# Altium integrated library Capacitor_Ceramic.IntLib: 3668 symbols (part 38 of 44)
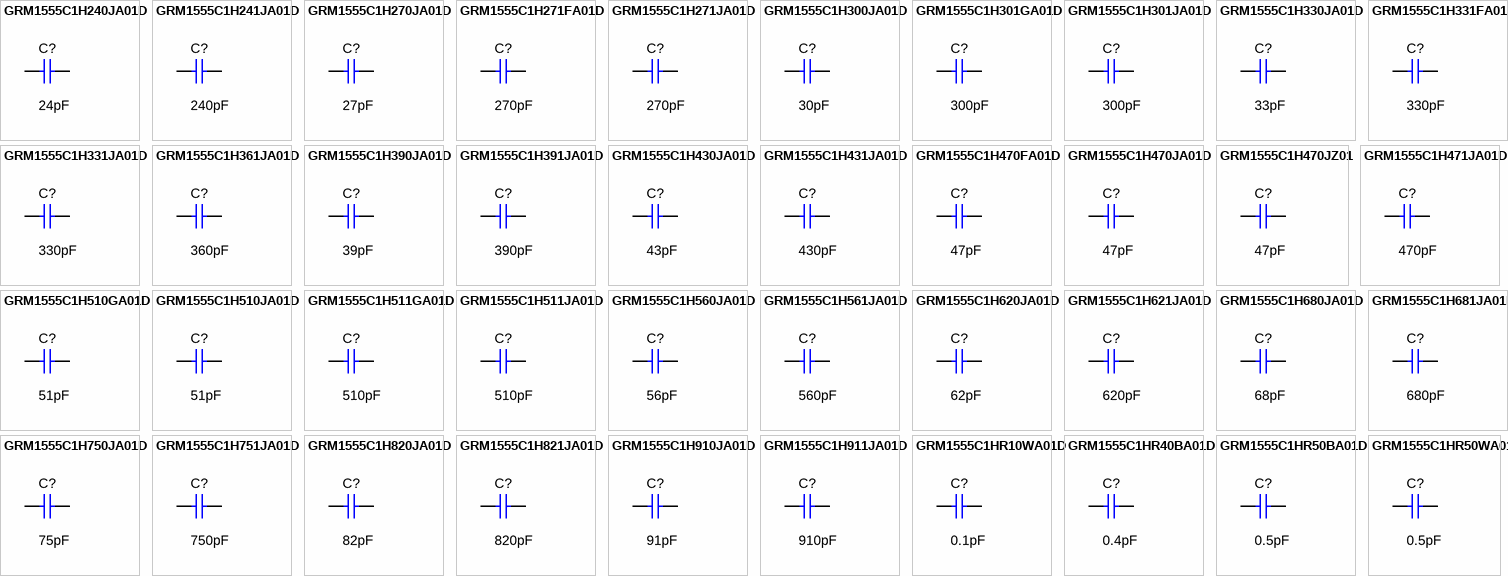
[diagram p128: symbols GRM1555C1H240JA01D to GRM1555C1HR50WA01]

## GRM1555C1H751JA01D
designator C?  ValueDisplayed: 750pF  (hidden comment: GRM1555C1H751JA01D)
CAP, CERM, 750 pF, 50 V,+/- 5%, C0G/NP0, 0402; Manufacturer: MuRata; Polarized: N; CompType: Capacitor; Value: 750pF; U/M: EA; Cap_F: 0.00000000075; Tolerance_%: 5; VDC_V: 50; Value2: 50V; TaMin_C: -55; TaMax_C: 125; Cap_Case: 0402; SizeArea_mm2: 0.5; SizeAreaWB_mm2: 3; SizeX_mm: 1; SizeZ_mm: 0.6; AEC Category: Q200
signal-integrity model Cap
simulation model Cap
footprint 0402
footprint 0402M
footprint 0402L
footprint 0402S
pins: 1, 2

## GRM1555C1H820JA01D
designator C?  ValueDisplayed: 82pF  (hidden comment: GRM1555C1H820JA01D)
CAP, CERM, 82 pF, 50 V,+/- 5%, C0G/NP0, 0402; Manufacturer: MuRata; Polarized: N; CompType: Capacitor; Value: 82pF; U/M: EA; Cap_F: 0.000000000082; Tolerance_%: 5; VDC_V: 50; Value2: 50V; TaMin_C: -55; TaMax_C: 125; Cap_Case: 0402; SizeArea_mm2: 0.5; SizeAreaWB_mm2: 3; SizeX_mm: 1; SizeZ_mm: 0.6; AEC Category: Q200
signal-integrity model Cap
simulation model Cap
footprint 0402
footprint 0402M
footprint 0402L
footprint 0402S
pins: 1, 2

## GRM1555C1H821JA01D
designator C?  ValueDisplayed: 820pF  (hidden comment: GRM1555C1H821JA01D)
CAP, CERM, 820 pF, 50 V,+/- 5%, C0G/NP0, 0402; Manufacturer: MuRata; Polarized: N; CompType: Capacitor; Value: 820pF; U/M: EA; Cap_F: 0.00000000082; Tolerance_%: 5; VDC_V: 50; Value2: 50V; TaMin_C: -55; TaMax_C: 125; Cap_Case: 0402; SizeArea_mm2: 0.5; SizeAreaWB_mm2: 3; SizeX_mm: 1; SizeZ_mm: 0.6; AEC Category: Q200
signal-integrity model Cap
simulation model Cap
footprint 0402
footprint 0402M
footprint 0402L
footprint 0402S
pins: 1, 2

## GRM1555C1H910JA01D
designator C?  ValueDisplayed: 91pF  (hidden comment: GRM1555C1H910JA01D)
CAP, CERM, 91 pF, 50 V,+/- 5%, C0G/NP0, 0402; Manufacturer: MuRata; Polarized: N; CompType: Capacitor; Value: 91pF; U/M: EA; Cap_F: 0.000000000091; Tolerance_%: 5; VDC_V: 50; Value2: 50V; TaMin_C: -55; TaMax_C: 125; Cap_Case: 0402; SizeArea_mm2: 0.5; SizeAreaWB_mm2: 3; SizeX_mm: 1; SizeZ_mm: 0.6; AEC Category: Q200; Green_Lifecycle: Active; Green_REACh: Passed
signal-integrity model Cap
simulation model Cap
footprint 0402
footprint 0402M
footprint 0402L
footprint 0402S
pins: 1, 2

## GRM1555C1H911JA01D
designator C?  ValueDisplayed: 910pF  (hidden comment: GRM1555C1H911JA01D)
CAP, CERM, 910 pF, 50 V,+/- 5%, C0G/NP0, 0402; Manufacturer: MuRata; Polarized: N; CompType: Capacitor; Value: 910pF; U/M: EA; Cap_F: 0.00000000091; Tolerance_%: 5; VDC_V: 50; Value2: 50V; TaMin_C: -55; TaMax_C: 125; Cap_Case: 0402; SizeArea_mm2: 0.5; SizeAreaWB_mm2: 3; SizeX_mm: 1; SizeZ_mm: 0.6; AEC Category: Q200
signal-integrity model Cap
simulation model Cap
footprint 0402
footprint 0402M
footprint 0402L
footprint 0402S
pins: 1, 2

## GRM1555C1HR10WA01D
designator C?  ValueDisplayed: 0.1pF  (hidden comment: GRM1555C1HR10WA01D)
CAP, CERM, 0.1pF, 50 V,+/- 50%, C0G/NP0, 0402; Manufacturer: MuRata; Polarized: N; CompType: Capacitor; U/M: EA; Cap_F: 0.0000000000001; Tolerance_%: 50; Value2: 50V; TaMin_C: -55; TaMax_C: 125; Cap_Case: 0402; SizeArea_mm2: 0.5; SizeAreaWB_mm2: 3; SizeX_mm: 1; SizeZ_mm: 0.6; AEC Category: Q200
signal-integrity model Cap
simulation model Cap
footprint 0402
footprint 0402M
footprint 0402L
footprint 0402S
pins: 1, 2

## GRM1555C1HR40BA01D
designator C?  ValueDisplayed: 0.4pF  (hidden comment: GRM1555C1HR40BA01D)
CAP, CERM, 0.4 pF, 50 V,+/- 25%, C0G/NP0, 0402; Manufacturer: MuRata; Polarized: N; CompType: Capacitor; Value: 0.4pF; U/M: EA; Cap_F: 0.0000000000004; Tolerance_%: 25; VDC_V: 50; Value2: 50V; TaMin_C: -55; TaMax_C: 125; Cap_Case: 0402; SizeArea_mm2: 0.5; SizeAreaWB_mm2: 3; SizeX_mm: 1; SizeZ_mm: 0.6; AEC Category: Q200
signal-integrity model Cap
simulation model Cap
footprint 0402
footprint 0402M
footprint 0402L
footprint 0402S
pins: 1, 2

## GRM1555C1HR50BA01D
designator C?  ValueDisplayed: 0.5pF  (hidden comment: GRM1555C1HR50BA01D)
CAP, CERM, 0.5 pF, 50 V,+/- 20%, C0G/NP0, 0402; Manufacturer: MuRata; Polarized: N; CompType: Capacitor; Value: 0.5pF; U/M: EA; Cap_F: 0.0000000000005; Tolerance_%: 20; VDC_V: 50; Value2: 50V; TaMin_C: -55; TaMax_C: 125; Cap_Case: 0402; SizeArea_mm2: 0.5; SizeAreaWB_mm2: 3; SizeX_mm: 1; SizeZ_mm: 0.6; AEC Category: Q200; Green_Lifecycle: Active; Green_REACh: Passed
signal-integrity model Cap
simulation model Cap
footprint 0402
footprint 0402M
footprint 0402L
footprint 0402S
pins: 1, 2

## GRM1555C1HR50WA01
designator C?  ValueDisplayed: 0.5pF  (hidden comment: GRM1555C1HR50WA01)
CAP, CERM, 0.5 pF, 50 V,+/- 10%, C0G/NP0, 0402; Manufacturer: MuRata; Polarized: N; CompType: Capacitor; Value: 0.5pF; U/M: EA; Cap_F: 0.0000000000005; Tolerance_%: 10; VDC_V: 50; Value2: 50V; TaMin_C: -55; TaMax_C: 125; Cap_Case: 0402; SizeArea_mm2: 0.5; SizeAreaWB_mm2: 3; SizeX_mm: 1; SizeZ_mm: 0.6; AEC Category: Q200
signal-integrity model Cap
simulation model Cap
footprint 0402
footprint 0402M
footprint 0402L
footprint 0402S
pins: 1, 2

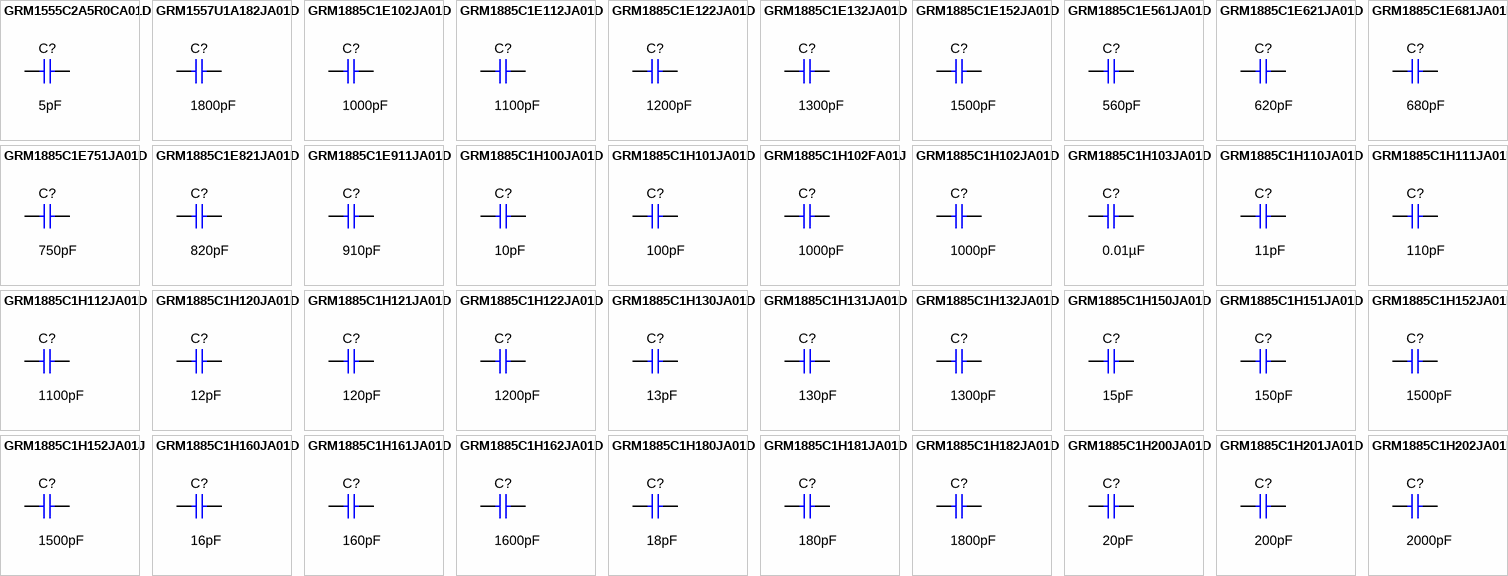
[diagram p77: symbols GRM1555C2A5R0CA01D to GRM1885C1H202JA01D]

## GRM1555C2A5R0CA01D
designator C?  ValueDisplayed: 5pF  (hidden comment: GRM1555C2A5R0CA01D)
CAP, CERM, 5 pF, 100 V,+/- 5%, C0G/NP0, 0402; Manufacturer: MuRata; Polarized: N; CompType: Capacitor; Value: 5pF; U/M: EA; Cap_F: 0.000000000005; Tolerance_%: 5; VDC_V: 100; Value2: 100V; TaMin_C: -55; TaMax_C: 125; Cap_Case: 0402; SizeArea_mm2: 0.5; SizeAreaWB_mm2: 3; SizeX_mm: 1; SizeZ_mm: 0.6; AEC Category: Q200
signal-integrity model Cap
simulation model Cap
footprint 0402
footprint 0402M
footprint 0402L
footprint 0402S
pins: 1, 2

## GRM1557U1A182JA01D
designator C?  ValueDisplayed: 1800pF  (hidden comment: GRM1557U1A182JA01D)
CAP, CERM, 1800 pF, 10 V,+/- 5%, U2J, 0402; Manufacturer: MuRata; Polarized: N; CompType: Capacitor; Value: 1800pF; U/M: EA; Cap_F: 0.0000000018; Tolerance_%: 5; VDC_V: 10; Value2: 10V; TaMin_C: -55; TaMax_C: 125; Cap_Case: 0402; SizeArea_mm2: 0.5; SizeAreaWB_mm2: 3; SizeX_mm: 1; SizeZ_mm: 0.6; AEC Category: Q200
signal-integrity model Cap
simulation model Cap
footprint 0402
footprint 0402M
footprint 0402L
footprint 0402S
pins: 1, 2

## GRM1885C1E102JA01D
designator C?  ValueDisplayed: 1000pF  (hidden comment: GRM1885C1E102JA01D)
CAP, CERM, 1000 pF, 25 V,+/- 5%, C0G/NP0, 0603; Manufacturer: MuRata; Polarized: N; CompType: Capacitor; Value: 1000pF; U/M: EA; Cap_F: 0.000000001; Tolerance_%: 5; VDC_V: 25; Value2: 25V; TaMin_C: -55; TaMax_C: 125; Cap_Case: 0603; SizeArea_mm2: 1.28; SizeAreaWB_mm2: 4.68; SizeX_mm: 1.6; SizeY_mm: 0.8; SizeZ_mm: 1; AEC Category: Q200; Green_Lifecycle: Active; Green_REACh: Passed
signal-integrity model Cap
simulation model Cap
footprint 0603
footprint 0603M
footprint 0603L
footprint 0603_HV
footprint 0603S
pins: 1, 2

## GRM1885C1E112JA01D
designator C?  ValueDisplayed: 1100pF  (hidden comment: GRM1885C1E112JA01D)
CAP, CERM, 1100 pF, 25 V,+/- 5%, C0G/NP0, 0603; Manufacturer: MuRata; Polarized: N; CompType: Capacitor; Value: 1100pF; U/M: EA; Cap_F: 0.0000000011; Tolerance_%: 5; VDC_V: 25; Value2: 25V; TaMin_C: -55; TaMax_C: 125; Cap_Case: 0603; SizeArea_mm2: 1.28; SizeAreaWB_mm2: 4.68; SizeX_mm: 1.6; SizeY_mm: 0.8; SizeZ_mm: 1; AEC Category: Q200
signal-integrity model Cap
simulation model Cap
footprint 0603
footprint 0603M
footprint 0603L
footprint 0603_HV
footprint 0603S
pins: 1, 2

## GRM1885C1E122JA01D
designator C?  ValueDisplayed: 1200pF  (hidden comment: GRM1885C1E122JA01D)
CAP, CERM, 1200 pF, 25 V,+/- 5%, C0G/NP0, 0603; Manufacturer: MuRata; Polarized: N; CompType: Capacitor; Value: 1200pF; U/M: EA; Cap_F: 0.0000000012; Tolerance_%: 5; VDC_V: 25; Value2: 25V; TaMin_C: -55; TaMax_C: 125; Cap_Case: 0603; SizeArea_mm2: 1.28; SizeAreaWB_mm2: 4.68; SizeX_mm: 1.6; SizeY_mm: 0.8; SizeZ_mm: 1; AEC Category: Q200
signal-integrity model Cap
simulation model Cap
footprint 0603
footprint 0603M
footprint 0603L
footprint 0603_HV
footprint 0603S
pins: 1, 2

## GRM1885C1E132JA01D
designator C?  ValueDisplayed: 1300pF  (hidden comment: GRM1885C1E132JA01D)
CAP, CERM, 1300 pF, 25 V,+/- 5%, C0G/NP0, 0603; Manufacturer: MuRata; Polarized: N; CompType: Capacitor; Value: 1300pF; U/M: EA; Cap_F: 0.0000000013; Tolerance_%: 5; VDC_V: 25; Value2: 25V; TaMin_C: -55; TaMax_C: 125; Cap_Case: 0603; SizeArea_mm2: 1.28; SizeAreaWB_mm2: 4.68; SizeX_mm: 1.6; SizeY_mm: 0.8; SizeZ_mm: 1; AEC Category: Q200
signal-integrity model Cap
simulation model Cap
footprint 0603
footprint 0603M
footprint 0603L
footprint 0603_HV
footprint 0603S
pins: 1, 2

## GRM1885C1E152JA01D
designator C?  ValueDisplayed: 1500pF  (hidden comment: GRM1885C1E152JA01D)
CAP, CERM, 1500 pF, 25 V,+/- 5%, C0G/NP0, 0603; Manufacturer: MuRata; Polarized: N; CompType: Capacitor; Value: 1500pF; U/M: EA; Cap_F: 0.0000000015; Tolerance_%: 5; VDC_V: 25; Value2: 25V; TaMin_C: -55; TaMax_C: 125; Cap_Case: 0603; SizeArea_mm2: 1.28; SizeAreaWB_mm2: 4.68; SizeX_mm: 1.6; SizeY_mm: 0.8; SizeZ_mm: 1; AEC Category: Q200
signal-integrity model Cap
simulation model Cap
footprint 0603
footprint 0603M
footprint 0603L
footprint 0603_HV
footprint 0603S
pins: 1, 2

## GRM1885C1E561JA01D
designator C?  ValueDisplayed: 560pF  (hidden comment: GRM1885C1E561JA01D)
CAP, CERM, 560 pF, 25 V,+/- 5%, C0G/NP0, 0603; Manufacturer: MuRata; Polarized: N; CompType: Capacitor; Value: 560pF; U/M: EA; Cap_F: 0.00000000056; Tolerance_%: 5; VDC_V: 25; Value2: 25V; TaMin_C: -55; TaMax_C: 125; Cap_Case: 0603; SizeArea_mm2: 1.28; SizeAreaWB_mm2: 4.68; SizeX_mm: 1.6; SizeY_mm: 0.8; SizeZ_mm: 1; AEC Category: Q200
signal-integrity model Cap
simulation model Cap
footprint 0603
footprint 0603M
footprint 0603L
footprint 0603_HV
footprint 0603S
pins: 1, 2

## GRM1885C1E621JA01D
designator C?  ValueDisplayed: 620pF  (hidden comment: GRM1885C1E621JA01D)
CAP, CERM, 620 pF, 25 V,+/- 5%, C0G/NP0, 0603; Manufacturer: MuRata; Polarized: N; CompType: Capacitor; Value: 620pF; U/M: EA; Cap_F: 0.00000000062; Tolerance_%: 5; VDC_V: 25; Value2: 25V; TaMin_C: -55; TaMax_C: 125; Cap_Case: 0603; SizeArea_mm2: 1.28; SizeAreaWB_mm2: 4.68; SizeX_mm: 1.6; SizeY_mm: 0.8; SizeZ_mm: 1; AEC Category: Q200
signal-integrity model Cap
simulation model Cap
footprint 0603
footprint 0603M
footprint 0603L
footprint 0603_HV
footprint 0603S
pins: 1, 2

## GRM1885C1E681JA01D
designator C?  ValueDisplayed: 680pF  (hidden comment: GRM1885C1E681JA01D)
CAP, CERM, 680 pF, 25 V,+/- 5%, C0G/NP0, 0603; Manufacturer: MuRata; Polarized: N; CompType: Capacitor; Value: 680pF; U/M: EA; Cap_F: 0.00000000068; Tolerance_%: 5; VDC_V: 25; Value2: 25V; TaMin_C: -55; TaMax_C: 125; Cap_Case: 0603; SizeArea_mm2: 1.28; SizeAreaWB_mm2: 4.68; SizeX_mm: 1.6; SizeY_mm: 0.8; SizeZ_mm: 1; AEC Category: Q200
signal-integrity model Cap
simulation model Cap
footprint 0603
footprint 0603M
footprint 0603L
footprint 0603_HV
footprint 0603S
pins: 1, 2

## GRM1885C1E751JA01D
designator C?  ValueDisplayed: 750pF  (hidden comment: GRM1885C1E751JA01D)
CAP, CERM, 750 pF, 25 V,+/- 5%, C0G/NP0, 0603; Manufacturer: MuRata; Polarized: N; CompType: Capacitor; Value: 750pF; U/M: EA; Cap_F: 0.00000000075; Tolerance_%: 5; VDC_V: 25; Value2: 25V; TaMin_C: -55; TaMax_C: 125; Cap_Case: 0603; SizeArea_mm2: 1.28; SizeAreaWB_mm2: 4.68; SizeX_mm: 1.6; SizeY_mm: 0.8; SizeZ_mm: 1; AEC Category: Q200
signal-integrity model Cap
simulation model Cap
footprint 0603
footprint 0603M
footprint 0603L
footprint 0603_HV
footprint 0603S
pins: 1, 2

## GRM1885C1E821JA01D
designator C?  ValueDisplayed: 820pF  (hidden comment: GRM1885C1E821JA01D)
CAP, CERM, 820 pF, 25 V,+/- 5%, C0G/NP0, 0603; Manufacturer: MuRata; Polarized: N; CompType: Capacitor; Value: 820pF; U/M: EA; Cap_F: 0.00000000082; Tolerance_%: 5; VDC_V: 25; Value2: 25V; TaMin_C: -55; TaMax_C: 125; Cap_Case: 0603; SizeArea_mm2: 1.28; SizeAreaWB_mm2: 4.68; SizeX_mm: 1.6; SizeY_mm: 0.8; SizeZ_mm: 1; AEC Category: Q200
signal-integrity model Cap
simulation model Cap
footprint 0603
footprint 0603M
footprint 0603L
footprint 0603_HV
footprint 0603S
pins: 1, 2

## GRM1885C1E911JA01D
designator C?  ValueDisplayed: 910pF  (hidden comment: GRM1885C1E911JA01D)
CAP, CERM, 910 pF, 25 V,+/- 5%, C0G/NP0, 0603; Manufacturer: MuRata; Polarized: N; CompType: Capacitor; Value: 910pF; U/M: EA; Cap_F: 0.00000000091; Tolerance_%: 5; VDC_V: 25; Value2: 25V; TaMin_C: -55; TaMax_C: 125; Cap_Case: 0603; SizeArea_mm2: 1.28; SizeAreaWB_mm2: 4.68; SizeX_mm: 1.6; SizeY_mm: 0.8; SizeZ_mm: 1; AEC Category: Q200
signal-integrity model Cap
simulation model Cap
footprint 0603
footprint 0603M
footprint 0603L
footprint 0603_HV
footprint 0603S
pins: 1, 2

## GRM1885C1H100JA01D
designator C?  ValueDisplayed: 10pF  (hidden comment: GRM1885C1H100JA01D)
CAP, CERM, 10 pF, 50 V,+/- 5%, C0G/NP0, 0603; Manufacturer: MuRata; Polarized: N; CompType: Capacitor; Value: 10pF; U/M: EA; Cap_F: 0.00000000001; Tolerance_%: 5; VDC_V: 50; Value2: 50V; TaMin_C: -55; TaMax_C: 125; Cap_Case: 0603; SizeArea_mm2: 1.28; SizeAreaWB_mm2: 4.68; SizeX_mm: 1.6; SizeY_mm: 0.8; SizeZ_mm: 1; AEC Category: Q200; Green_Lifecycle: Active; Green_REACh: Passed
signal-integrity model Cap
simulation model Cap
footprint 0603
footprint 0603M
footprint 0603L
footprint 0603_HV
footprint 0603S
pins: 1, 2

## GRM1885C1H101JA01D
designator C?  ValueDisplayed: 100pF  (hidden comment: GRM1885C1H101JA01D)
CAP, CERM, 100 pF, 50 V,+/- 5%, C0G/NP0, 0603; Manufacturer: MuRata; Polarized: N; CompType: Capacitor; Value: 100pF; U/M: EA; Cap_F: 0.0000000001; Tolerance_%: 5; VDC_V: 50; Value2: 50V; TaMin_C: -55; TaMax_C: 125; Cap_Case: 0603; SizeArea_mm2: 1.28; SizeAreaWB_mm2: 4.68; SizeX_mm: 1.6; SizeY_mm: 0.8; SizeZ_mm: 1; AEC Category: Q200; Green_Lifecycle: Active; Green_REACh: Passed
signal-integrity model Cap
simulation model Cap
footprint 0603
footprint 0603M
footprint 0603L
footprint 0603_HV
footprint 0603S
pins: 1, 2

## GRM1885C1H102FA01J
designator C?  ValueDisplayed: 1000pF  (hidden comment: GRM1885C1H102FA01J)
CAP, CERM, 1000 pF, 50 V,+/- 1%, C0G/NP0, 0603; Manufacturer: MuRata; Polarized: N; CompType: Capacitor; Value: 1000pF; U/M: EA; Cap_F: 0.000000001; Tolerance_%: 1; VDC_V: 50; Value2: 50V; TaMin_C: -55; TaMax_C: 125; Cap_Case: 0603; SizeArea_mm2: 1.28; SizeAreaWB_mm2: 4.68; SizeX_mm: 1.6; SizeY_mm: 0.8; AEC Category: Q200; Green_Lifecycle: Not Set; Green_REACh: Incomplete
signal-integrity model Cap
simulation model Cap
footprint 0603
footprint 0603M
footprint 0603L
footprint 0603_HV
footprint 0603S
pins: 1, 2

## GRM1885C1H102JA01D
designator C?  ValueDisplayed: 1000pF  (hidden comment: GRM1885C1H102JA01D)
CAP, CERM, 1000 pF, 50 V,+/- 5%, C0G/NP0, 0603; Manufacturer: MuRata; Polarized: N; CompType: Capacitor; Value: 1000pF; U/M: EA; Cap_F: 0.000000001; Tolerance_%: 5; VDC_V: 50; Value2: 50V; TaMin_C: -55; TaMax_C: 125; Cap_Case: 0603; SizeArea_mm2: 1.28; SizeAreaWB_mm2: 4.68; SizeX_mm: 1.6; SizeY_mm: 0.8; SizeZ_mm: 1; AEC Category: Q200; Green_Lifecycle: Active; Green_REACh: Passed
signal-integrity model Cap
simulation model Cap
footprint 0603
footprint 0603M
footprint 0603L
footprint 0603_HV
footprint 0603S
pins: 1, 2

## GRM1885C1H103JA01D
designator C?  ValueDisplayed: 0.01µF  (hidden comment: GRM1885C1H103JA01D)
CAP, CERM, 0.01 µF, 50 V,+/- 5%, C0G/NP0, 0603; Manufacturer: MuRata; Polarized: N; CompType: Capacitor; Value: 0.01uF; U/M: EA; Cap_F: 0.00000001; Tolerance_%: 5; VDC_V: 50; Value2: 50V; TaMin_C: -55; TaMax_C: 125; Cap_Case: 0603; SizeArea_mm2: 1.28; SizeAreaWB_mm2: 4.68; SizeX_mm: 1.6; SizeY_mm: 0.8; SizeZ_mm: 1; AEC Category: Q200
signal-integrity model Cap
simulation model Cap
footprint 0603
footprint 0603M
footprint 0603L
footprint 0603_HV
footprint 0603S
pins: 1, 2

## GRM1885C1H110JA01D
designator C?  ValueDisplayed: 11pF  (hidden comment: GRM1885C1H110JA01D)
CAP, CERM, 11 pF, 50 V,+/- 5%, C0G/NP0, 0603; Manufacturer: MuRata; Polarized: N; CompType: Capacitor; Value: 11pF; U/M: EA; Cap_F: 0.000000000011; Tolerance_%: 5; VDC_V: 50; Value2: 50V; TaMin_C: -55; TaMax_C: 125; Cap_Case: 0603; SizeArea_mm2: 1.28; SizeAreaWB_mm2: 4.68; SizeX_mm: 1.6; SizeY_mm: 0.8; SizeZ_mm: 1; AEC Category: Q200
signal-integrity model Cap
simulation model Cap
footprint 0603
footprint 0603M
footprint 0603L
footprint 0603_HV
footprint 0603S
pins: 1, 2

## GRM1885C1H111JA01D
designator C?  ValueDisplayed: 110pF  (hidden comment: GRM1885C1H111JA01D)
CAP, CERM, 110 pF, 50 V,+/- 5%, C0G/NP0, 0603; Manufacturer: MuRata; Polarized: N; CompType: Capacitor; Value: 110pF; U/M: EA; Cap_F: 0.00000000011; Tolerance_%: 5; VDC_V: 50; Value2: 50V; TaMin_C: -55; TaMax_C: 125; Cap_Case: 0603; SizeArea_mm2: 1.28; SizeAreaWB_mm2: 4.68; SizeX_mm: 1.6; SizeY_mm: 0.8; SizeZ_mm: 1; AEC Category: Q200
signal-integrity model Cap
simulation model Cap
footprint 0603
footprint 0603M
footprint 0603L
footprint 0603_HV
footprint 0603S
pins: 1, 2

## GRM1885C1H112JA01D
designator C?  ValueDisplayed: 1100pF  (hidden comment: GRM1885C1H112JA01D)
CAP, CERM, 1100 pF, 50 V,+/- 5%, C0G/NP0, 0603; Manufacturer: MuRata; Polarized: N; CompType: Capacitor; Value: 1100pF; U/M: EA; Cap_F: 0.0000000011; Tolerance_%: 5; VDC_V: 50; Value2: 50V; TaMin_C: -55; TaMax_C: 125; Cap_Case: 0603; SizeArea_mm2: 1.28; SizeAreaWB_mm2: 4.68; SizeX_mm: 1.6; SizeY_mm: 0.8; SizeZ_mm: 1; AEC Category: Q200
signal-integrity model Cap
simulation model Cap
footprint 0603
footprint 0603M
footprint 0603L
footprint 0603_HV
footprint 0603S
pins: 1, 2

## GRM1885C1H120JA01D
designator C?  ValueDisplayed: 12pF  (hidden comment: GRM1885C1H120JA01D)
CAP, CERM, 12 pF, 50 V,+/- 5%, C0G/NP0, 0603; Manufacturer: MuRata; Polarized: N; CompType: Capacitor; Value: 12pF; U/M: EA; Cap_F: 0.000000000012; Tolerance_%: 5; VDC_V: 50; Value2: 50V; TaMin_C: -55; TaMax_C: 125; Cap_Case: 0603; SizeArea_mm2: 1.28; SizeAreaWB_mm2: 4.68; SizeX_mm: 1.6; SizeY_mm: 0.8; SizeZ_mm: 1; AEC Category: Q200; Green_Lifecycle: Active; Green_REACh: Passed
signal-integrity model Cap
simulation model Cap
footprint 0603
footprint 0603M
footprint 0603L
footprint 0603_HV
footprint 0603S
pins: 1, 2

## GRM1885C1H121JA01D
designator C?  ValueDisplayed: 120pF  (hidden comment: GRM1885C1H121JA01D)
CAP, CERM, 120 pF, 50 V,+/- 5%, C0G/NP0, 0603; Manufacturer: MuRata; Polarized: N; CompType: Capacitor; Value: 120pF; U/M: EA; Cap_F: 0.00000000012; Tolerance_%: 5; VDC_V: 50; Value2: 50V; TaMin_C: -55; TaMax_C: 125; Cap_Case: 0603; SizeArea_mm2: 1.28; SizeAreaWB_mm2: 4.68; SizeX_mm: 1.6; SizeY_mm: 0.8; SizeZ_mm: 1; AEC Category: Q200; Green_Lifecycle: Active; Green_REACh: Passed
signal-integrity model Cap
simulation model Cap
footprint 0603
footprint 0603M
footprint 0603L
footprint 0603_HV
footprint 0603S
pins: 1, 2

## GRM1885C1H122JA01D
designator C?  ValueDisplayed: 1200pF  (hidden comment: GRM1885C1H122JA01D)
CAP, CERM, 1200 pF, 50 V,+/- 5%, C0G/NP0, 0603; Manufacturer: MuRata; Polarized: N; CompType: Capacitor; Value: 1200pF; U/M: EA; Cap_F: 0.0000000012; Tolerance_%: 5; VDC_V: 50; Value2: 50V; TaMin_C: -55; TaMax_C: 125; Cap_Case: 0603; SizeArea_mm2: 1.28; SizeAreaWB_mm2: 4.68; SizeX_mm: 1.6; SizeY_mm: 0.8; SizeZ_mm: 1; AEC Category: Q200; Green_Lifecycle: Active; Green_REACh: Passed
signal-integrity model Cap
simulation model Cap
footprint 0603
footprint 0603M
footprint 0603L
footprint 0603_HV
footprint 0603S
pins: 1, 2

## GRM1885C1H130JA01D
designator C?  ValueDisplayed: 13pF  (hidden comment: GRM1885C1H130JA01D)
CAP, CERM, 13 pF, 50 V,+/- 5%, C0G/NP0, 0603; Manufacturer: MuRata; Polarized: N; CompType: Capacitor; Value: 13pF; U/M: EA; Cap_F: 0.000000000013; Tolerance_%: 5; VDC_V: 50; Value2: 50V; TaMin_C: -55; TaMax_C: 125; Cap_Case: 0603; SizeArea_mm2: 1.28; SizeAreaWB_mm2: 4.68; SizeX_mm: 1.6; SizeY_mm: 0.8; SizeZ_mm: 1; AEC Category: Q200
signal-integrity model Cap
simulation model Cap
footprint 0603
footprint 0603M
footprint 0603L
footprint 0603_HV
footprint 0603S
pins: 1, 2

## GRM1885C1H131JA01D
designator C?  ValueDisplayed: 130pF  (hidden comment: GRM1885C1H131JA01D)
CAP, CERM, 130 pF, 50 V,+/- 5%, C0G/NP0, 0603; Manufacturer: MuRata; Polarized: N; CompType: Capacitor; Value: 130pF; U/M: EA; Cap_F: 0.00000000013; Tolerance_%: 5; VDC_V: 50; Value2: 50V; TaMin_C: -55; TaMax_C: 125; Cap_Case: 0603; SizeArea_mm2: 1.28; SizeAreaWB_mm2: 4.68; SizeX_mm: 1.6; SizeY_mm: 0.8; SizeZ_mm: 1; AEC Category: Q200; Green_Lifecycle: Active; Green_REACh: Passed
signal-integrity model Cap
simulation model Cap
footprint 0603
footprint 0603M
footprint 0603L
footprint 0603_HV
footprint 0603S
pins: 1, 2

## GRM1885C1H132JA01D
designator C?  ValueDisplayed: 1300pF  (hidden comment: GRM1885C1H132JA01D)
CAP, CERM, 1300 pF, 50 V,+/- 5%, C0G/NP0, 0603; Manufacturer: MuRata; Polarized: N; CompType: Capacitor; Value: 1300pF; U/M: EA; Cap_F: 0.0000000013; Tolerance_%: 5; VDC_V: 50; Value2: 50V; TaMin_C: -55; TaMax_C: 125; Cap_Case: 0603; SizeArea_mm2: 1.28; SizeAreaWB_mm2: 4.68; SizeX_mm: 1.6; SizeY_mm: 0.8; SizeZ_mm: 1; AEC Category: Q200
signal-integrity model Cap
simulation model Cap
footprint 0603
footprint 0603M
footprint 0603L
footprint 0603_HV
footprint 0603S
pins: 1, 2

## GRM1885C1H150JA01D
designator C?  ValueDisplayed: 15pF  (hidden comment: GRM1885C1H150JA01D)
CAP, CERM, 15 pF, 50 V,+/- 5%, C0G/NP0, 0603; Manufacturer: MuRata; Polarized: N; CompType: Capacitor; Value: 15pF; U/M: EA; Cap_F: 0.000000000015; Tolerance_%: 5; VDC_V: 50; Value2: 50V; TaMin_C: -55; TaMax_C: 125; Cap_Case: 0603; SizeArea_mm2: 1.28; SizeAreaWB_mm2: 4.68; SizeX_mm: 1.6; SizeY_mm: 0.8; SizeZ_mm: 1; AEC Category: Q200
signal-integrity model Cap
simulation model Cap
footprint 0603
footprint 0603M
footprint 0603L
footprint 0603_HV
footprint 0603S
pins: 1, 2

## GRM1885C1H151JA01D
designator C?  ValueDisplayed: 150pF  (hidden comment: GRM1885C1H151JA01D)
CAP, CERM, 150 pF, 50 V,+/- 5%, C0G/NP0, 0603; Manufacturer: MuRata; Polarized: N; CompType: Capacitor; Value: 150pF; U/M: EA; Cap_F: 0.00000000015; Tolerance_%: 5; VDC_V: 50; Value2: 50V; TaMin_C: -55; TaMax_C: 125; Cap_Case: 0603; SizeArea_mm2: 1.28; SizeAreaWB_mm2: 4.68; SizeX_mm: 1.6; SizeY_mm: 0.8; SizeZ_mm: 1; AEC Category: Q200; Green_Lifecycle: Active; Green_REACh: Passed
signal-integrity model Cap
simulation model Cap
footprint 0603
footprint 0603M
footprint 0603L
footprint 0603_HV
footprint 0603S
pins: 1, 2

## GRM1885C1H152JA01D
designator C?  ValueDisplayed: 1500pF  (hidden comment: GRM1885C1H152JA01D)
CAP, CERM, 1500 pF, 50 V,+/- 5%, C0G/NP0, 0603; Manufacturer: MuRata; Polarized: N; CompType: Capacitor; Value: 1500pF; U/M: EA; Cap_F: 0.0000000015; Tolerance_%: 5; VDC_V: 50; Value2: 50V; TaMin_C: -55; TaMax_C: 125; Cap_Case: 0603; SizeArea_mm2: 1.28; SizeAreaWB_mm2: 4.68; SizeX_mm: 1.6; SizeY_mm: 0.8; SizeZ_mm: 1; AEC Category: Q200; Green_Lifecycle: Active; Green_REACh: Passed
signal-integrity model Cap
simulation model Cap
footprint 0603
footprint 0603M
footprint 0603L
footprint 0603_HV
footprint 0603S
pins: 1, 2

## GRM1885C1H152JA01J
designator C?  ValueDisplayed: 1500pF  (hidden comment: GRM1885C1H152JA01J)
CAP, CERM, 1500 pF, 50 V,+/- 5%, C0G/NP0, 0603; Manufacturer: MuRata; Polarized: N; CompType: Capacitor; Value: 1500pF; U/M: EA; Cap_F: 0.0000000015; Tolerance_%: 5; VDC_V: 50; Value2: 50V; TaMin_C: -55; TaMax_C: 125; Cap_Case: 0603; SizeArea_mm2: 1.28; SizeAreaWB_mm2: 4.68; SizeX_mm: 1.6; SizeY_mm: 0.8; SizeZ_mm: 1; AEC Category: Q200
signal-integrity model Cap
simulation model Cap
footprint 0603
footprint 0603M
footprint 0603L
footprint 0603_HV
footprint 0603S
pins: 1, 2

## GRM1885C1H160JA01D
designator C?  ValueDisplayed: 16pF  (hidden comment: GRM1885C1H160JA01D)
CAP, CERM, 16 pF, 50 V,+/- 5%, C0G/NP0, 0603; Manufacturer: MuRata; Polarized: N; CompType: Capacitor; Value: 16pF; U/M: EA; Cap_F: 0.000000000016; Tolerance_%: 5; VDC_V: 50; Value2: 50V; TaMin_C: -55; TaMax_C: 125; Cap_Case: 0603; SizeArea_mm2: 1.28; SizeAreaWB_mm2: 4.68; SizeX_mm: 1.6; SizeY_mm: 0.8; SizeZ_mm: 1; AEC Category: Q200
signal-integrity model Cap
simulation model Cap
footprint 0603
footprint 0603M
footprint 0603L
footprint 0603_HV
footprint 0603S
pins: 1, 2

## GRM1885C1H161JA01D
designator C?  ValueDisplayed: 160pF  (hidden comment: GRM1885C1H161JA01D)
CAP, CERM, 160 pF, 50 V,+/- 5%, C0G/NP0, 0603; Manufacturer: MuRata; Polarized: N; CompType: Capacitor; Value: 160pF; U/M: EA; Cap_F: 0.00000000016; Tolerance_%: 5; VDC_V: 50; Value2: 50V; TaMin_C: -55; TaMax_C: 125; Cap_Case: 0603; SizeArea_mm2: 1.28; SizeAreaWB_mm2: 4.68; SizeX_mm: 1.6; SizeY_mm: 0.8; SizeZ_mm: 1; AEC Category: Q200; Green_Lifecycle: Active; Green_REACh: Passed
signal-integrity model Cap
simulation model Cap
footprint 0603
footprint 0603M
footprint 0603L
footprint 0603_HV
footprint 0603S
pins: 1, 2

## GRM1885C1H162JA01D
designator C?  ValueDisplayed: 1600pF  (hidden comment: GRM1885C1H162JA01D)
CAP, CERM, 1600 pF, 50 V,+/- 5%, C0G/NP0, 0603; Manufacturer: MuRata; Polarized: N; CompType: Capacitor; Value: 1600pF; U/M: EA; Cap_F: 0.0000000016; Tolerance_%: 5; VDC_V: 50; Value2: 50V; TaMin_C: -55; TaMax_C: 125; Cap_Case: 0603; SizeArea_mm2: 1.28; SizeAreaWB_mm2: 4.68; SizeX_mm: 1.6; SizeY_mm: 0.8; SizeZ_mm: 1; AEC Category: Q200
signal-integrity model Cap
simulation model Cap
footprint 0603
footprint 0603M
footprint 0603L
footprint 0603_HV
footprint 0603S
pins: 1, 2

## GRM1885C1H180JA01D
designator C?  ValueDisplayed: 18pF  (hidden comment: GRM1885C1H180JA01D)
CAP, CERM, 18 pF, 50 V,+/- 5%, C0G/NP0, 0603; Manufacturer: MuRata; Polarized: N; CompType: Capacitor; Value: 18pF; U/M: EA; Cap_F: 0.000000000018; Tolerance_%: 5; VDC_V: 50; Value2: 50V; TaMin_C: -55; TaMax_C: 125; Cap_Case: 0603; SizeArea_mm2: 1.28; SizeAreaWB_mm2: 4.68; SizeX_mm: 1.6; SizeY_mm: 0.8; SizeZ_mm: 1; AEC Category: Q200; Green_Lifecycle: Active; Green_REACh: Passed
signal-integrity model Cap
simulation model Cap
footprint 0603
footprint 0603M
footprint 0603L
footprint 0603_HV
footprint 0603S
pins: 1, 2

## GRM1885C1H181JA01D
designator C?  ValueDisplayed: 180pF  (hidden comment: GRM1885C1H181JA01D)
CAP, CERM, 180 pF, 50 V,+/- 5%, C0G/NP0, 0603; Manufacturer: MuRata; Polarized: N; CompType: Capacitor; Value: 180pF; U/M: EA; Cap_F: 0.00000000018; Tolerance_%: 5; VDC_V: 50; Value2: 50V; TaMin_C: -55; TaMax_C: 125; Cap_Case: 0603; SizeArea_mm2: 1.28; SizeAreaWB_mm2: 4.68; SizeX_mm: 1.6; SizeY_mm: 0.8; SizeZ_mm: 1; AEC Category: Q200; Green_Lifecycle: Active; Green_REACh: Passed
signal-integrity model Cap
simulation model Cap
footprint 0603
footprint 0603M
footprint 0603L
footprint 0603_HV
footprint 0603S
pins: 1, 2

## GRM1885C1H182JA01D
designator C?  ValueDisplayed: 1800pF  (hidden comment: GRM1885C1H182JA01D)
CAP, CERM, 1800 pF, 50 V,+/- 5%, C0G/NP0, 0603; Manufacturer: MuRata; Polarized: N; CompType: Capacitor; Value: 1800pF; U/M: EA; Cap_F: 0.0000000018; Tolerance_%: 5; VDC_V: 50; Value2: 50V; TaMin_C: -55; TaMax_C: 125; Cap_Case: 0603; SizeArea_mm2: 1.28; SizeAreaWB_mm2: 4.68; SizeX_mm: 1.6; SizeY_mm: 0.8; SizeZ_mm: 1; AEC Category: Q200
signal-integrity model Cap
simulation model Cap
footprint 0603
footprint 0603M
footprint 0603L
footprint 0603_HV
footprint 0603S
pins: 1, 2

## GRM1885C1H200JA01D
designator C?  ValueDisplayed: 20pF  (hidden comment: GRM1885C1H200JA01D)
CAP, CERM, 20 pF, 50 V,+/- 5%, C0G/NP0, 0603; Manufacturer: MuRata; Polarized: N; CompType: Capacitor; Value: 20pF; U/M: EA; Cap_F: 0.00000000002; Tolerance_%: 5; VDC_V: 50; Value2: 50V; TaMin_C: -55; TaMax_C: 125; Cap_Case: 0603; SizeArea_mm2: 1.28; SizeAreaWB_mm2: 4.68; SizeX_mm: 1.6; SizeY_mm: 0.8; SizeZ_mm: 1; AEC Category: Q200; Green_Lifecycle: Active; Green_REACh: Passed
signal-integrity model Cap
simulation model Cap
footprint 0603
footprint 0603M
footprint 0603L
footprint 0603_HV
footprint 0603S
pins: 1, 2

## GRM1885C1H201JA01D
designator C?  ValueDisplayed: 200pF  (hidden comment: GRM1885C1H201JA01D)
CAP, CERM, 200 pF, 50 V,+/- 5%, C0G/NP0, 0603; Manufacturer: MuRata; Polarized: N; CompType: Capacitor; Value: 200pF; U/M: EA; Cap_F: 0.0000000002; Tolerance_%: 5; VDC_V: 50; Value2: 50V; TaMin_C: -55; TaMax_C: 125; Cap_Case: 0603; SizeArea_mm2: 1.28; SizeAreaWB_mm2: 4.68; SizeX_mm: 1.6; SizeY_mm: 0.8; SizeZ_mm: 1; AEC Category: Q200; Green_Lifecycle: Active; Green_REACh: Passed
signal-integrity model Cap
simulation model Cap
footprint 0603
footprint 0603M
footprint 0603L
footprint 0603_HV
footprint 0603S
pins: 1, 2

## GRM1885C1H202JA01D
designator C?  ValueDisplayed: 2000pF  (hidden comment: GRM1885C1H202JA01D)
CAP, CERM, 2000 pF, 50 V,+/- 5%, C0G/NP0, 0603; Manufacturer: MuRata; Polarized: N; CompType: Capacitor; Value: 2000pF; U/M: EA; Cap_F: 0.000000002; Tolerance_%: 5; VDC_V: 50; Value2: 50V; TaMin_C: -55; TaMax_C: 125; Cap_Case: 0603; SizeArea_mm2: 1.28; SizeAreaWB_mm2: 4.68; SizeX_mm: 1.6; SizeY_mm: 0.8; SizeZ_mm: 1; AEC Category: Q200; Green_Lifecycle: Active; Green_REACh: Passed
signal-integrity model Cap
simulation model Cap
footprint 0603
footprint 0603M
footprint 0603L
footprint 0603_HV
footprint 0603S
pins: 1, 2

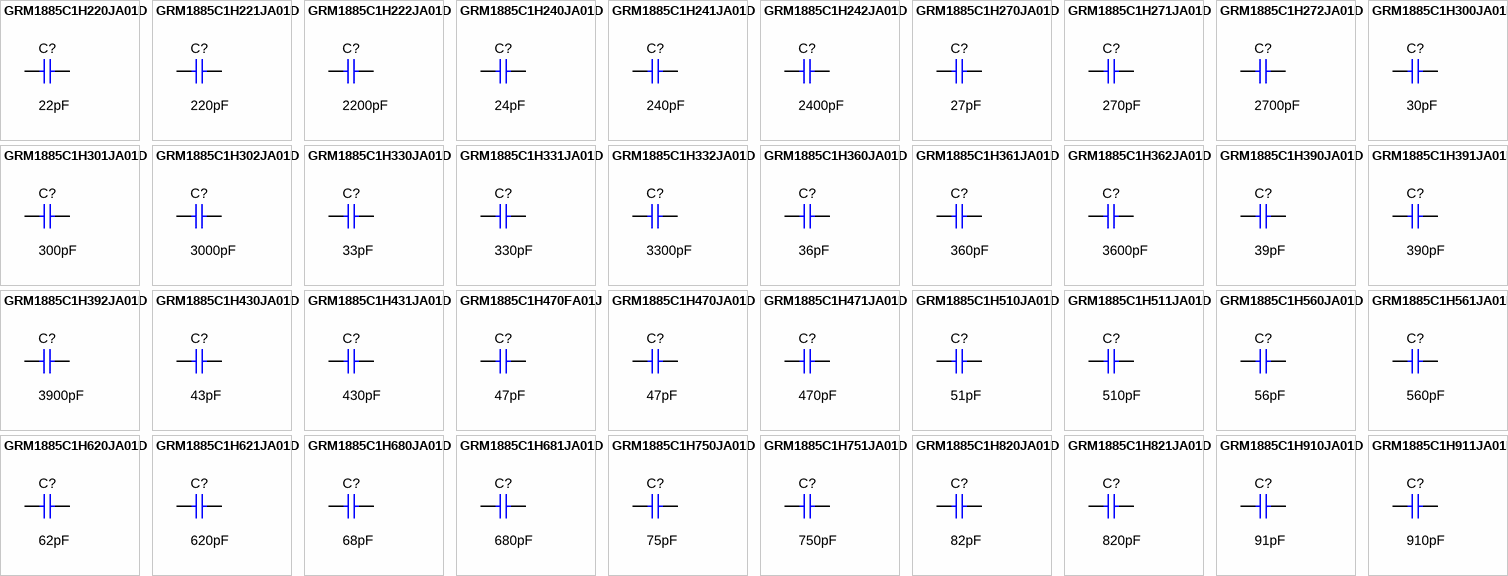
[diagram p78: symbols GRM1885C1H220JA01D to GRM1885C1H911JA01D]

## GRM1885C1H220JA01D
designator C?  ValueDisplayed: 22pF  (hidden comment: GRM1885C1H220JA01D)
CAP, CERM, 22 pF, 50 V,+/- 5%, C0G/NP0, 0603; Manufacturer: MuRata; Polarized: N; CompType: Capacitor; Value: 22pF; U/M: EA; Cap_F: 0.000000000022; Tolerance_%: 5; VDC_V: 50; Value2: 50V; TaMin_C: -55; TaMax_C: 125; Cap_Case: 0603; SizeArea_mm2: 1.28; SizeAreaWB_mm2: 4.68; SizeX_mm: 1.6; SizeY_mm: 0.8; SizeZ_mm: 1; AEC Category: Q200; Green_Lifecycle: Active; Green_REACh: Passed
signal-integrity model Cap
simulation model Cap
footprint 0603
footprint 0603M
footprint 0603L
footprint 0603_HV
footprint 0603S
pins: 1, 2

## GRM1885C1H221JA01D
designator C?  ValueDisplayed: 220pF  (hidden comment: GRM1885C1H221JA01D)
CAP, CERM, 220 pF, 50 V,+/- 5%, C0G/NP0, 0603; Manufacturer: MuRata; Polarized: N; CompType: Capacitor; Value: 220pF; U/M: EA; Cap_F: 0.00000000022; Tolerance_%: 5; VDC_V: 50; Value2: 50V; TaMin_C: -55; TaMax_C: 125; Cap_Case: 0603; SizeArea_mm2: 1.28; SizeAreaWB_mm2: 4.68; SizeX_mm: 1.6; SizeY_mm: 0.8; SizeZ_mm: 1; AEC Category: Q200; Green_Lifecycle: Active; Green_REACh: Passed
signal-integrity model Cap
simulation model Cap
footprint 0603
footprint 0603M
footprint 0603L
footprint 0603_HV
footprint 0603S
pins: 1, 2

## GRM1885C1H222JA01D
designator C?  ValueDisplayed: 2200pF  (hidden comment: GRM1885C1H222JA01D)
CAP, CERM, 2200 pF, 50 V,+/- 5%, C0G/NP0, 0603; Manufacturer: MuRata; Polarized: N; CompType: Capacitor; Value: 2200pF; U/M: EA; Cap_F: 0.0000000022; Tolerance_%: 5; VDC_V: 50; Value2: 50V; TaMin_C: -55; TaMax_C: 125; Cap_Case: 0603; SizeArea_mm2: 1.28; SizeAreaWB_mm2: 4.68; SizeX_mm: 1.6; SizeY_mm: 0.8; SizeZ_mm: 1; AEC Category: Q200; Green_Lifecycle: Active; Green_REACh: Passed
signal-integrity model Cap
simulation model Cap
footprint 0603
footprint 0603M
footprint 0603L
footprint 0603_HV
footprint 0603S
pins: 1, 2

## GRM1885C1H240JA01D
designator C?  ValueDisplayed: 24pF  (hidden comment: GRM1885C1H240JA01D)
CAP, CERM, 24 pF, 50 V,+/- 5%, C0G/NP0, 0603; Manufacturer: MuRata; Polarized: N; CompType: Capacitor; Value: 24pF; U/M: EA; Cap_F: 0.000000000024; Tolerance_%: 5; VDC_V: 50; Value2: 50V; TaMin_C: -55; TaMax_C: 125; Cap_Case: 0603; SizeArea_mm2: 1.28; SizeAreaWB_mm2: 4.68; SizeX_mm: 1.6; SizeY_mm: 0.8; SizeZ_mm: 1; AEC Category: Q200
signal-integrity model Cap
simulation model Cap
footprint 0603
footprint 0603M
footprint 0603L
footprint 0603_HV
footprint 0603S
pins: 1, 2

## GRM1885C1H241JA01D
designator C?  ValueDisplayed: 240pF  (hidden comment: GRM1885C1H241JA01D)
CAP, CERM, 240 pF, 50 V,+/- 5%, C0G/NP0, 0603; Manufacturer: MuRata; Polarized: N; CompType: Capacitor; Value: 240pF; U/M: EA; Cap_F: 0.00000000024; Tolerance_%: 5; VDC_V: 50; Value2: 50V; TaMin_C: -55; TaMax_C: 125; Cap_Case: 0603; SizeArea_mm2: 1.28; SizeAreaWB_mm2: 4.68; SizeX_mm: 1.6; SizeY_mm: 0.8; SizeZ_mm: 1; AEC Category: Q200
signal-integrity model Cap
simulation model Cap
footprint 0603
footprint 0603M
footprint 0603L
footprint 0603_HV
footprint 0603S
pins: 1, 2

## GRM1885C1H242JA01D
designator C?  ValueDisplayed: 2400pF  (hidden comment: GRM1885C1H242JA01D)
CAP, CERM, 2400 pF, 50 V,+/- 5%, C0G/NP0, 0603; Manufacturer: MuRata; Polarized: N; CompType: Capacitor; Value: 2400pF; U/M: EA; Cap_F: 0.0000000024; Tolerance_%: 5; VDC_V: 50; Value2: 50V; TaMin_C: -55; TaMax_C: 125; Cap_Case: 0603; SizeArea_mm2: 1.28; SizeAreaWB_mm2: 4.68; SizeX_mm: 1.6; SizeY_mm: 0.8; SizeZ_mm: 1; AEC Category: Q200
signal-integrity model Cap
simulation model Cap
footprint 0603
footprint 0603M
footprint 0603L
footprint 0603_HV
footprint 0603S
pins: 1, 2

## GRM1885C1H270JA01D
designator C?  ValueDisplayed: 27pF  (hidden comment: GRM1885C1H270JA01D)
CAP, CERM, 27 pF, 50 V,+/- 5%, C0G/NP0, 0603; Manufacturer: MuRata; Polarized: N; CompType: Capacitor; Value: 27pF; U/M: EA; Cap_F: 0.000000000027; Tolerance_%: 5; VDC_V: 50; Value2: 50V; TaMin_C: -55; TaMax_C: 125; Cap_Case: 0603; SizeArea_mm2: 1.28; SizeAreaWB_mm2: 4.68; SizeX_mm: 1.6; SizeY_mm: 0.8; SizeZ_mm: 1; AEC Category: Q200; Green_Lifecycle: Active; Green_REACh: Passed
signal-integrity model Cap
simulation model Cap
footprint 0603
footprint 0603M
footprint 0603L
footprint 0603_HV
footprint 0603S
pins: 1, 2

## GRM1885C1H271JA01D
designator C?  ValueDisplayed: 270pF  (hidden comment: GRM1885C1H271JA01D)
CAP, CERM, 270 pF, 50 V,+/- 5%, C0G/NP0, 0603; Manufacturer: MuRata; Polarized: N; CompType: Capacitor; Value: 270pF; U/M: EA; Cap_F: 0.00000000027; Tolerance_%: 5; VDC_V: 50; Value2: 50V; TaMin_C: -55; TaMax_C: 125; Cap_Case: 0603; SizeArea_mm2: 1.28; SizeAreaWB_mm2: 4.68; SizeX_mm: 1.6; SizeY_mm: 0.8; SizeZ_mm: 1; AEC Category: Q200; Green_Lifecycle: Active; Green_REACh: Passed
signal-integrity model Cap
simulation model Cap
footprint 0603
footprint 0603M
footprint 0603L
footprint 0603_HV
footprint 0603S
pins: 1, 2

## GRM1885C1H272JA01D
designator C?  ValueDisplayed: 2700pF  (hidden comment: GRM1885C1H272JA01D)
CAP, CERM, 2700 pF, 50 V,+/- 5%, C0G/NP0, 0603; Manufacturer: MuRata; Polarized: N; CompType: Capacitor; Value: 2700pF; U/M: EA; Cap_F: 0.0000000027; Tolerance_%: 5; VDC_V: 50; Value2: 50V; TaMin_C: -55; TaMax_C: 125; Cap_Case: 0603; SizeArea_mm2: 1.28; SizeAreaWB_mm2: 4.68; SizeX_mm: 1.6; SizeY_mm: 0.8; SizeZ_mm: 1; AEC Category: Q200; Green_Lifecycle: Active; Green_REACh: Passed
signal-integrity model Cap
simulation model Cap
footprint 0603
footprint 0603M
footprint 0603L
footprint 0603_HV
footprint 0603S
pins: 1, 2

## GRM1885C1H300JA01D
designator C?  ValueDisplayed: 30pF  (hidden comment: GRM1885C1H300JA01D)
CAP, CERM, 30 pF, 50 V,+/- 5%, C0G/NP0, 0603; Manufacturer: MuRata; Polarized: N; CompType: Capacitor; Value: 30pF; U/M: EA; Cap_F: 0.00000000003; Tolerance_%: 5; VDC_V: 50; Value2: 50V; TaMin_C: -55; TaMax_C: 125; Cap_Case: 0603; SizeArea_mm2: 1.28; SizeAreaWB_mm2: 4.68; SizeX_mm: 1.6; SizeY_mm: 0.8; SizeZ_mm: 1; AEC Category: Q200; Green_Lifecycle: Active; Green_REACh: Passed
signal-integrity model Cap
simulation model Cap
footprint 0603
footprint 0603M
footprint 0603L
footprint 0603_HV
footprint 0603S
pins: 1, 2

## GRM1885C1H301JA01D
designator C?  ValueDisplayed: 300pF  (hidden comment: GRM1885C1H301JA01D)
CAP, CERM, 300 pF, 50 V,+/- 5%, C0G/NP0, 0603; Manufacturer: MuRata; Polarized: N; CompType: Capacitor; Value: 300pF; U/M: EA; Cap_F: 0.0000000003; Tolerance_%: 5; VDC_V: 50; Value2: 50V; TaMin_C: -55; TaMax_C: 125; Cap_Case: 0603; SizeArea_mm2: 1.28; SizeAreaWB_mm2: 4.68; SizeX_mm: 1.6; SizeY_mm: 0.8; SizeZ_mm: 1; AEC Category: Q200; Green_Lifecycle: Active; Green_REACh: Passed
signal-integrity model Cap
simulation model Cap
footprint 0603
footprint 0603M
footprint 0603L
footprint 0603_HV
footprint 0603S
pins: 1, 2

## GRM1885C1H302JA01D
designator C?  ValueDisplayed: 3000pF  (hidden comment: GRM1885C1H302JA01D)
CAP, CERM, 3000 pF, 50 V,+/- 5%, C0G/NP0, 0603; Manufacturer: MuRata; Polarized: N; CompType: Capacitor; Value: 3000pF; U/M: EA; Cap_F: 0.000000003; Tolerance_%: 5; VDC_V: 50; Value2: 50V; TaMin_C: -55; TaMax_C: 125; Cap_Case: 0603; SizeArea_mm2: 1.28; SizeAreaWB_mm2: 4.68; SizeX_mm: 1.6; SizeY_mm: 0.8; SizeZ_mm: 1; AEC Category: Q200; Green_Lifecycle: Active; Green_REACh: Passed
signal-integrity model Cap
simulation model Cap
footprint 0603
footprint 0603M
footprint 0603L
footprint 0603_HV
footprint 0603S
pins: 1, 2

## GRM1885C1H330JA01D
designator C?  ValueDisplayed: 33pF  (hidden comment: GRM1885C1H330JA01D)
CAP, CERM, 33 pF, 50 V,+/- 5%, C0G/NP0, 0603; Manufacturer: MuRata; Polarized: N; CompType: Capacitor; Value: 33pF; U/M: EA; Cap_F: 0.000000000033; Tolerance_%: 5; VDC_V: 50; Value2: 50V; TaMin_C: -55; TaMax_C: 125; Cap_Case: 0603; SizeArea_mm2: 1.28; SizeAreaWB_mm2: 4.68; SizeX_mm: 1.6; SizeY_mm: 0.8; SizeZ_mm: 1; AEC Category: Q200; Green_Lifecycle: Active; Green_REACh: Passed
signal-integrity model Cap
simulation model Cap
footprint 0603
footprint 0603M
footprint 0603L
footprint 0603_HV
footprint 0603S
pins: 1, 2

## GRM1885C1H331JA01D
designator C?  ValueDisplayed: 330pF  (hidden comment: GRM1885C1H331JA01D)
CAP, CERM, 330 pF, 50 V,+/- 5%, C0G/NP0, 0603; Manufacturer: MuRata; Polarized: N; CompType: Capacitor; Value: 330pF; U/M: EA; Cap_F: 0.00000000033; Tolerance_%: 5; VDC_V: 50; Value2: 50V; TaMin_C: -55; TaMax_C: 125; Cap_Case: 0603; SizeArea_mm2: 1.28; SizeAreaWB_mm2: 4.68; SizeX_mm: 1.6; SizeY_mm: 0.8; SizeZ_mm: 1; AEC Category: Q200; Green_Lifecycle: Active; Green_REACh: Passed
signal-integrity model Cap
simulation model Cap
footprint 0603
footprint 0603M
footprint 0603L
footprint 0603_HV
footprint 0603S
pins: 1, 2

## GRM1885C1H332JA01D
designator C?  ValueDisplayed: 3300pF  (hidden comment: GRM1885C1H332JA01D)
CAP, CERM, 3300 pF, 50 V,+/- 5%, C0G/NP0, 0603; Manufacturer: MuRata; Polarized: N; CompType: Capacitor; Value: 3300pF; U/M: EA; Cap_F: 0.0000000033; Tolerance_%: 5; VDC_V: 50; Value2: 50V; TaMin_C: -55; TaMax_C: 125; Cap_Case: 0603; SizeArea_mm2: 1.28; SizeAreaWB_mm2: 4.68; SizeX_mm: 1.6; SizeY_mm: 0.8; SizeZ_mm: 1; AEC Category: Q200; Green_Lifecycle: Active; Green_REACh: Passed
signal-integrity model Cap
simulation model Cap
footprint 0603
footprint 0603M
footprint 0603L
footprint 0603_HV
footprint 0603S
pins: 1, 2

## GRM1885C1H360JA01D
designator C?  ValueDisplayed: 36pF  (hidden comment: GRM1885C1H360JA01D)
CAP, CERM, 36 pF, 50 V,+/- 5%, C0G/NP0, 0603; Manufacturer: MuRata; Polarized: N; CompType: Capacitor; Value: 36pF; U/M: EA; Cap_F: 0.000000000036; Tolerance_%: 5; VDC_V: 50; Value2: 50V; TaMin_C: -55; TaMax_C: 125; Cap_Case: 0603; SizeArea_mm2: 1.28; SizeAreaWB_mm2: 4.68; SizeX_mm: 1.6; SizeY_mm: 0.8; SizeZ_mm: 1; AEC Category: Q200
signal-integrity model Cap
simulation model Cap
footprint 0603
footprint 0603M
footprint 0603L
footprint 0603_HV
footprint 0603S
pins: 1, 2

## GRM1885C1H361JA01D
designator C?  ValueDisplayed: 360pF  (hidden comment: GRM1885C1H361JA01D)
CAP, CERM, 360 pF, 50 V,+/- 5%, C0G/NP0, 0603; Manufacturer: MuRata; Polarized: N; CompType: Capacitor; Value: 360pF; U/M: EA; Cap_F: 0.00000000036; Tolerance_%: 5; VDC_V: 50; Value2: 50V; TaMin_C: -55; TaMax_C: 125; Cap_Case: 0603; SizeArea_mm2: 1.28; SizeAreaWB_mm2: 4.68; SizeX_mm: 1.6; SizeY_mm: 0.8; SizeZ_mm: 1; AEC Category: Q200
signal-integrity model Cap
simulation model Cap
footprint 0603
footprint 0603M
footprint 0603L
footprint 0603_HV
footprint 0603S
pins: 1, 2

## GRM1885C1H362JA01D
designator C?  ValueDisplayed: 3600pF  (hidden comment: GRM1885C1H362JA01D)
CAP, CERM, 3600 pF, 50 V,+/- 5%, C0G/NP0, 0603; Manufacturer: MuRata; Polarized: N; CompType: Capacitor; Value: 3600pF; U/M: EA; Cap_F: 0.0000000036; Tolerance_%: 5; VDC_V: 50; Value2: 50V; TaMin_C: -55; TaMax_C: 125; Cap_Case: 0603; SizeArea_mm2: 1.28; SizeAreaWB_mm2: 4.68; SizeX_mm: 1.6; SizeY_mm: 0.8; SizeZ_mm: 1; AEC Category: Q200
signal-integrity model Cap
simulation model Cap
footprint 0603
footprint 0603M
footprint 0603L
footprint 0603_HV
footprint 0603S
pins: 1, 2

## GRM1885C1H390JA01D
designator C?  ValueDisplayed: 39pF  (hidden comment: GRM1885C1H390JA01D)
CAP, CERM, 39 pF, 50 V,+/- 5%, C0G/NP0, 0603; Manufacturer: MuRata; Polarized: N; CompType: Capacitor; Value: 39pF; U/M: EA; Cap_F: 0.000000000039; Tolerance_%: 5; VDC_V: 50; Value2: 50V; TaMin_C: -55; TaMax_C: 125; Cap_Case: 0603; SizeArea_mm2: 1.28; SizeAreaWB_mm2: 4.68; SizeX_mm: 1.6; SizeY_mm: 0.8; SizeZ_mm: 1; AEC Category: Q200; Green_Lifecycle: Active; Green_REACh: Passed
signal-integrity model Cap
simulation model Cap
footprint 0603
footprint 0603M
footprint 0603L
footprint 0603_HV
footprint 0603S
pins: 1, 2

## GRM1885C1H391JA01D
designator C?  ValueDisplayed: 390pF  (hidden comment: GRM1885C1H391JA01D)
CAP, CERM, 390 pF, 50 V,+/- 5%, C0G/NP0, 0603; Manufacturer: MuRata; Polarized: N; CompType: Capacitor; Value: 390pF; U/M: EA; Cap_F: 0.00000000039; Tolerance_%: 5; VDC_V: 50; Value2: 50V; TaMin_C: -55; TaMax_C: 125; Cap_Case: 0603; SizeArea_mm2: 1.28; SizeAreaWB_mm2: 4.68; SizeX_mm: 1.6; SizeY_mm: 0.8; SizeZ_mm: 1; AEC Category: Q200
signal-integrity model Cap
simulation model Cap
footprint 0603
footprint 0603M
footprint 0603L
footprint 0603_HV
footprint 0603S
pins: 1, 2

## GRM1885C1H392JA01D
designator C?  ValueDisplayed: 3900pF  (hidden comment: GRM1885C1H392JA01D)
CAP, CERM, 3900 pF, 50 V,+/- 5%, C0G/NP0, 0603; Manufacturer: MuRata; Polarized: N; CompType: Capacitor; Value: 3900pF; U/M: EA; Cap_F: 0.0000000039; Tolerance_%: 5; VDC_V: 50; Value2: 50V; TaMin_C: -55; TaMax_C: 125; Cap_Case: 0603; SizeArea_mm2: 1.28; SizeAreaWB_mm2: 4.68; SizeX_mm: 1.6; SizeY_mm: 0.8; SizeZ_mm: 1; AEC Category: Q200
signal-integrity model Cap
simulation model Cap
footprint 0603
footprint 0603M
footprint 0603L
footprint 0603_HV
footprint 0603S
pins: 1, 2

## GRM1885C1H430JA01D
designator C?  ValueDisplayed: 43pF  (hidden comment: GRM1885C1H430JA01D)
CAP, CERM, 43 pF, 50 V,+/- 5%, C0G/NP0, 0603; Manufacturer: MuRata; Polarized: N; CompType: Capacitor; Value: 43pF; U/M: EA; Cap_F: 0.000000000043; Tolerance_%: 5; VDC_V: 50; Value2: 50V; TaMin_C: -55; TaMax_C: 125; Cap_Case: 0603; SizeArea_mm2: 1.28; SizeAreaWB_mm2: 4.68; SizeX_mm: 1.6; SizeY_mm: 0.8; SizeZ_mm: 1; AEC Category: Q200
signal-integrity model Cap
simulation model Cap
footprint 0603
footprint 0603M
footprint 0603L
footprint 0603_HV
footprint 0603S
pins: 1, 2

## GRM1885C1H431JA01D
designator C?  ValueDisplayed: 430pF  (hidden comment: GRM1885C1H431JA01D)
CAP, CERM, 430 pF, 50 V,+/- 5%, C0G/NP0, 0603; Manufacturer: MuRata; Polarized: N; CompType: Capacitor; Value: 430pF; U/M: EA; Cap_F: 0.00000000043; Tolerance_%: 5; VDC_V: 50; Value2: 50V; TaMin_C: -55; TaMax_C: 125; Cap_Case: 0603; SizeArea_mm2: 1.28; SizeAreaWB_mm2: 4.68; SizeX_mm: 1.6; SizeY_mm: 0.8; SizeZ_mm: 1; AEC Category: Q200
signal-integrity model Cap
simulation model Cap
footprint 0603
footprint 0603M
footprint 0603L
footprint 0603_HV
footprint 0603S
pins: 1, 2

## GRM1885C1H470FA01J
designator C?  ValueDisplayed: 47pF  (hidden comment: GRM1885C1H470FA01J)
CAP, CERM, 47 pF, 50 V,+/- 1%, C0G/NP0, 0603; Manufacturer: MuRata; Polarized: N; CompType: Capacitor; Value: 47pF; U/M: EA; Cap_F: 0.000000000047; Tolerance_%: 1; VDC_V: 50; Value2: 50V; TaMin_C: -55; TaMax_C: 125; Cap_Case: 0603; SizeArea_mm2: 1.28; SizeAreaWB_mm2: 4.68; SizeX_mm: 1.6; SizeY_mm: 0.8; AEC Category: Q200; Green_Lifecycle: Not Set; Green_REACh: Incomplete
signal-integrity model Cap
simulation model Cap
footprint 0603
footprint 0603M
footprint 0603L
footprint 0603_HV
footprint 0603S
pins: 1, 2

## GRM1885C1H470JA01D
designator C?  ValueDisplayed: 47pF  (hidden comment: GRM1885C1H470JA01D)
CAP, CERM, 47 pF, 50 V,+/- 5%, C0G/NP0, 0603; Manufacturer: MuRata; Polarized: N; CompType: Capacitor; Value: 47pF; U/M: EA; Cap_F: 0.000000000047; Tolerance_%: 5; VDC_V: 50; Value2: 50V; TaMin_C: -55; TaMax_C: 125; Cap_Case: 0603; SizeArea_mm2: 1.28; SizeAreaWB_mm2: 4.68; SizeX_mm: 1.6; SizeY_mm: 0.8; SizeZ_mm: 1; AEC Category: Q200; Green_Lifecycle: Active; Green_REACh: Passed
signal-integrity model Cap
simulation model Cap
footprint 0603
footprint 0603M
footprint 0603L
footprint 0603_HV
footprint 0603S
pins: 1, 2

## GRM1885C1H471JA01D
designator C?  ValueDisplayed: 470pF  (hidden comment: GRM1885C1H471JA01D)
CAP, CERM, 470 pF, 50 V,+/- 5%, C0G/NP0, 0603; Manufacturer: MuRata; Polarized: N; CompType: Capacitor; Value: 470pF; U/M: EA; Cap_F: 0.00000000047; Tolerance_%: 5; VDC_V: 50; Value2: 50V; TaMin_C: -55; TaMax_C: 125; Cap_Case: 0603; SizeArea_mm2: 1.28; SizeAreaWB_mm2: 4.68; SizeX_mm: 1.6; SizeY_mm: 0.8; SizeZ_mm: 1; AEC Category: Q200; Green_Lifecycle: Active; Green_REACh: Passed
signal-integrity model Cap
simulation model Cap
footprint 0603
footprint 0603M
footprint 0603L
footprint 0603_HV
footprint 0603S
pins: 1, 2

## GRM1885C1H510JA01D
designator C?  ValueDisplayed: 51pF  (hidden comment: GRM1885C1H510JA01D)
CAP, CERM, 51 pF, 50 V,+/- 5%, C0G/NP0, 0603; Manufacturer: MuRata; Polarized: N; CompType: Capacitor; Value: 51pF; U/M: EA; Cap_F: 0.000000000051; Tolerance_%: 5; VDC_V: 50; Value2: 50V; TaMin_C: -55; TaMax_C: 125; Cap_Case: 0603; SizeArea_mm2: 1.28; SizeAreaWB_mm2: 4.68; SizeX_mm: 1.6; SizeY_mm: 0.8; SizeZ_mm: 1; AEC Category: Q200; Green_Lifecycle: Active; Green_REACh: Passed
signal-integrity model Cap
simulation model Cap
footprint 0603
footprint 0603M
footprint 0603L
footprint 0603_HV
footprint 0603S
pins: 1, 2

## GRM1885C1H511JA01D
designator C?  ValueDisplayed: 510pF  (hidden comment: GRM1885C1H511JA01D)
CAP, CERM, 510 pF, 50 V,+/- 5%, C0G/NP0, 0603; Manufacturer: MuRata; Polarized: N; CompType: Capacitor; Value: 510pF; U/M: EA; Cap_F: 0.00000000051; Tolerance_%: 5; VDC_V: 50; Value2: 50V; TaMin_C: -55; TaMax_C: 125; Cap_Case: 0603; SizeArea_mm2: 1.28; SizeAreaWB_mm2: 4.68; SizeX_mm: 1.6; SizeY_mm: 0.8; SizeZ_mm: 1; AEC Category: Q200
signal-integrity model Cap
simulation model Cap
footprint 0603
footprint 0603M
footprint 0603L
footprint 0603_HV
footprint 0603S
pins: 1, 2

## GRM1885C1H560JA01D
designator C?  ValueDisplayed: 56pF  (hidden comment: GRM1885C1H560JA01D)
CAP, CERM, 56 pF, 50 V,+/- 5%, C0G/NP0, 0603; Manufacturer: MuRata; Polarized: N; CompType: Capacitor; Value: 56pF; U/M: EA; Cap_F: 0.000000000056; Tolerance_%: 5; VDC_V: 50; Value2: 50V; TaMin_C: -55; TaMax_C: 125; Cap_Case: 0603; SizeArea_mm2: 1.28; SizeAreaWB_mm2: 4.68; SizeX_mm: 1.6; SizeY_mm: 0.8; SizeZ_mm: 1; AEC Category: Q200; Green_Lifecycle: Active; Green_REACh: Passed
signal-integrity model Cap
simulation model Cap
footprint 0603
footprint 0603M
footprint 0603L
footprint 0603_HV
footprint 0603S
pins: 1, 2

## GRM1885C1H561JA01D
designator C?  ValueDisplayed: 560pF  (hidden comment: GRM1885C1H561JA01D)
CAP, CERM, 560 pF, 50 V,+/- 5%, C0G/NP0, 0603; Manufacturer: MuRata; Polarized: N; CompType: Capacitor; Value: 560pF; U/M: EA; Cap_F: 0.00000000056; Tolerance_%: 5; VDC_V: 50; Value2: 50V; TaMin_C: -55; TaMax_C: 125; Cap_Case: 0603; SizeArea_mm2: 1.28; SizeAreaWB_mm2: 4.68; SizeX_mm: 1.6; SizeY_mm: 0.8; SizeZ_mm: 1; AEC Category: Q200; Green_Lifecycle: Active; Green_REACh: Passed
signal-integrity model Cap
simulation model Cap
footprint 0603
footprint 0603M
footprint 0603L
footprint 0603_HV
footprint 0603S
pins: 1, 2

## GRM1885C1H620JA01D
designator C?  ValueDisplayed: 62pF  (hidden comment: GRM1885C1H620JA01D)
CAP, CERM, 62 pF, 50 V,+/- 5%, C0G/NP0, 0603; Manufacturer: MuRata; Polarized: N; CompType: Capacitor; Value: 62pF; U/M: EA; Cap_F: 0.000000000062; Tolerance_%: 5; VDC_V: 50; Value2: 50V; TaMin_C: -55; TaMax_C: 125; Cap_Case: 0603; SizeArea_mm2: 1.28; SizeAreaWB_mm2: 4.68; SizeX_mm: 1.6; SizeY_mm: 0.8; SizeZ_mm: 1; AEC Category: Q200
signal-integrity model Cap
simulation model Cap
footprint 0603
footprint 0603M
footprint 0603L
footprint 0603_HV
footprint 0603S
pins: 1, 2

## GRM1885C1H621JA01D
designator C?  ValueDisplayed: 620pF  (hidden comment: GRM1885C1H621JA01D)
CAP, CERM, 620 pF, 50 V,+/- 5%, C0G/NP0, 0603; Manufacturer: MuRata; Polarized: N; CompType: Capacitor; Value: 620pF; U/M: EA; Cap_F: 0.00000000062; Tolerance_%: 5; VDC_V: 50; Value2: 50V; TaMin_C: -55; TaMax_C: 125; Cap_Case: 0603; SizeArea_mm2: 1.28; SizeAreaWB_mm2: 4.68; SizeX_mm: 1.6; SizeY_mm: 0.8; SizeZ_mm: 1; AEC Category: Q200
signal-integrity model Cap
simulation model Cap
footprint 0603
footprint 0603M
footprint 0603L
footprint 0603_HV
footprint 0603S
pins: 1, 2

## GRM1885C1H680JA01D
designator C?  ValueDisplayed: 68pF  (hidden comment: GRM1885C1H680JA01D)
CAP, CERM, 68 pF, 50 V,+/- 5%, C0G/NP0, 0603; Manufacturer: MuRata; Polarized: N; CompType: Capacitor; Value: 68pF; U/M: EA; Cap_F: 0.000000000068; Tolerance_%: 5; VDC_V: 50; Value2: 50V; TaMin_C: -55; TaMax_C: 125; Cap_Case: 0603; SizeArea_mm2: 1.28; SizeAreaWB_mm2: 4.68; SizeX_mm: 1.6; SizeY_mm: 0.8; SizeZ_mm: 1; AEC Category: Q200; Green_Lifecycle: Active; Green_REACh: Passed
signal-integrity model Cap
simulation model Cap
footprint 0603
footprint 0603M
footprint 0603L
footprint 0603_HV
footprint 0603S
pins: 1, 2

## GRM1885C1H681JA01D
designator C?  ValueDisplayed: 680pF  (hidden comment: GRM1885C1H681JA01D)
CAP, CERM, 680 pF, 50 V,+/- 5%, C0G/NP0, 0603; Manufacturer: MuRata; Polarized: N; CompType: Capacitor; Value: 680pF; U/M: EA; Cap_F: 0.00000000068; Tolerance_%: 5; VDC_V: 50; Value2: 50V; TaMin_C: -55; TaMax_C: 125; Cap_Case: 0603; SizeArea_mm2: 1.28; SizeAreaWB_mm2: 4.68; SizeX_mm: 1.6; SizeY_mm: 0.8; SizeZ_mm: 1; AEC Category: Q200
signal-integrity model Cap
simulation model Cap
footprint 0603
footprint 0603M
footprint 0603L
footprint 0603_HV
footprint 0603S
pins: 1, 2

## GRM1885C1H750JA01D
designator C?  ValueDisplayed: 75pF  (hidden comment: GRM1885C1H750JA01D)
CAP, CERM, 75 pF, 50 V,+/- 5%, C0G/NP0, 0603; Manufacturer: MuRata; Polarized: N; CompType: Capacitor; Value: 75pF; U/M: EA; Cap_F: 0.000000000075; Tolerance_%: 5; VDC_V: 50; Value2: 50V; TaMin_C: -55; TaMax_C: 125; Cap_Case: 0603; SizeArea_mm2: 1.28; SizeAreaWB_mm2: 4.68; SizeX_mm: 1.6; SizeY_mm: 0.8; SizeZ_mm: 1; AEC Category: Q200
signal-integrity model Cap
simulation model Cap
footprint 0603
footprint 0603M
footprint 0603L
footprint 0603_HV
footprint 0603S
pins: 1, 2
